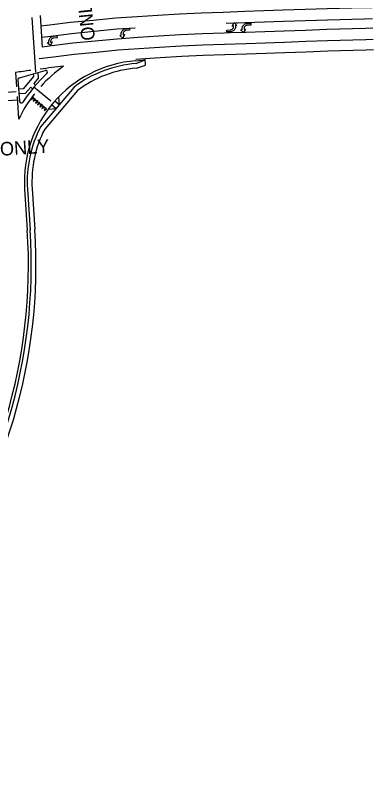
# Model space of a CAD drawing. Extents: x 979036 to 996074, y 1836928 to 1845163.
# Drawn here: x 982672 to 983052, y 1841869 to 1842691 of the extents above; entities that cross this region are included whole.
import ezdxf

# ---------------------------------------------------------------- set-up
doc = ezdxf.new("R2010")
doc.units = 0
for name, color, linetype in [('R_Proposed Road', 7, 'Continuous'), ('STRIPE_White Crosswalk', 7, 'Continuous'), ('STRIPE_White Stopbar', 7, 'Continuous'), ('STRIPE_White Turn Arrow', 7, 'Continuous'), ('STRIPE_WHITE_10_30 SKIP', 7, 'Continuous'), ('STRIPE_White_6in', 7, 'Continuous'), ('STRIPE_White_ONLY', 7, 'Continuous'), ('STRIPE_White_Yield Tri', 7, 'Continuous'), ('STRIPE_Yellow Dbl 6in', 7, 'Continuous'), ('STRIPE_Yellow_10_30 SKIP', 7, 'Continuous')]:
    doc.layers.add(name, color=color, linetype=linetype)

msp = doc.modelspace()

# ---------------------------------------------------------------- linework, layer by layer
at = {"layer": 'R_Proposed Road'}
for p, q in [((982799.93, 1842644.75), (982809.75, 1842645.53)), ((982800.05, 1842643.26), (982809.84, 1842644.23)), ((982800.28, 1842640.27), (982809.84, 1842644.23)), ((982810.26, 1842638.37), (982809.75, 1842645.53)), ((982676.32, 1842625.22), (982703.74, 1842632.98)), ((982800.68, 1842635.28), (982810.26, 1842638.37)), ((982691.2, 1842626.36), (982680.23, 1842613.3)), ((982691, 1842629.38), (982691.2, 1842626.36)), ((982696.32, 1842624.68), (982691.61, 1842619.08)), ((982695.92, 1842630.77), (982696.32, 1842624.68)), ((982674.87, 1842623.17), (982676.36, 1842600.28)), ((982688.39, 1842615.25), (982682.68, 1842608.45)), ((982690.41, 1842613.53), (982688.39, 1842615.25)), ((982693.65, 1842617.35), (982691.61, 1842619.08)), ((982734.54, 1842615.29), (982699.1, 1842573.54)), ((982680.23, 1842613.3), (982675.53, 1842613)), ((982682.68, 1842608.45), (982675.86, 1842608.01)), ((982738, 1842611.63), (982703.27, 1842570.73)), ((982718.44, 1842596.33), (982713.87, 1842600.21)), ((982717.78, 1842604.44), (982718.44, 1842596.33)), ((982707.09, 1842591.85), (982715.21, 1842592.51)), ((982715.21, 1842592.51), (982710.63, 1842596.39)), ((982681.97, 1842506.79), (982684.79, 1842463.51)), ((982684.96, 1842506.98), (982687.79, 1842463.71)), ((982689.95, 1842507.31), (982692.78, 1842464.03))]:
    msp.add_line(p, q, dxfattribs=at)
for centre, radius, start, end in [((982810.19, 1842515.16), 128.5, 94.53005, 183.73532), ((982810.19, 1842515.16), 125.5, 94.53005, 127.0701), ((982704.28, 1842631.05), 2, 312.42262, 105.79571), ((982810.19, 1842515.16), 120.5, 94.53005, 126.81019), ((982676.87, 1842623.3), 2, 105.79571, 183.73532), ((982810.19, 1842515.16), 155, 132.42262, 147.10941), ((982678.36, 1842600.42), 2, 183.73532, 327.10941), ((982810.19, 1842515.16), 125.5, 152.27794, 183.73532), ((982810.19, 1842515.16), 120.5, 152.53786, 183.73532), ((982120.82, 1842426.69), 565.17, 283.27832, 3.73532), ((982120.82, 1842426.69), 568.17, 283.27832, 3.73532), ((982120.82, 1842426.69), 573.17, 283.27832, 3.73532)]:
    msp.add_arc(centre, radius, start, end, dxfattribs=at)
at = {"layer": 'STRIPE_White Crosswalk'}
for p, q in [((982689.61, 1842689.06), (982693.4, 1842630.94)), ((982709.68, 1842600.21), (982691.87, 1842615.27)), ((982673.08, 1842610.34), (982627.82, 1842607.14))]:
    msp.add_line(p, q, dxfattribs=at)
at = {"layer": 'STRIPE_White Stopbar'}
for p, q in [((982698.49, 1842691.16), (982700.68, 1842657.65)), ((982674.29, 1842601.39), (982650.34, 1842599.83))]:
    msp.add_line(p, q, dxfattribs=at)
at = {"layer": 'STRIPE_White Turn Arrow'}
for points in [[(982902.15, 1842679.91), (982904.25, 1842683.73), (982907.41, 1842680.73), (982905.77, 1842680.47), (982905.81, 1842679.81), (982905.81, 1842679.23), (982905.69, 1842678.42), (982905.38, 1842677.46), (982905.01, 1842676.71), (982904.5, 1842676.08), (982903.91, 1842675.35), (982903.24, 1842674.92), (982902.53, 1842674.44), (982901.6, 1842674.12), (982900.63, 1842673.91), (982896.73, 1842673.74), (982896.64, 1842675.74), (982900.23, 1842675.93), (982900.92, 1842676.02), (982901.64, 1842676.28), (982902.39, 1842676.7), (982903, 1842677.31), (982903.2, 1842677.62), (982903.54, 1842678.26), (982903.74, 1842679.04), (982903.81, 1842679.78), (982903.79, 1842680.17)], [(982916.56, 1842676.88), (982914.44, 1842673.07), (982911.29, 1842676.09), (982912.94, 1842676.34), (982912.9, 1842677), (982912.91, 1842677.58), (982913.03, 1842678.39), (982913.34, 1842679.35), (982913.72, 1842680.1), (982914.23, 1842680.72), (982914.83, 1842681.45), (982915.49, 1842681.88), (982916.21, 1842682.35), (982917.14, 1842682.67), (982918.11, 1842682.88), (982922.01, 1842683.02), (982922.09, 1842681.02), (982918.5, 1842680.85), (982917.81, 1842680.77), (982917.09, 1842680.51), (982916.33, 1842680.09), (982915.72, 1842679.48), (982915.52, 1842679.17), (982915.18, 1842678.54), (982914.98, 1842677.76), (982914.9, 1842677.02), (982914.91, 1842676.63)], [(982788.13, 1842671.16), (982786.21, 1842667.24), (982782.91, 1842670.1), (982784.54, 1842670.43), (982784.47, 1842671.09), (982784.44, 1842671.67), (982784.53, 1842672.48), (982784.79, 1842673.46), (982785.13, 1842674.23), (982785.61, 1842674.88), (982786.16, 1842675.63), (982786.81, 1842676.1), (982787.5, 1842676.61), (982788.41, 1842676.97), (982789.37, 1842677.23), (982793.26, 1842677.57), (982793.44, 1842675.57), (982789.86, 1842675.22), (982789.18, 1842675.1), (982788.48, 1842674.81), (982787.74, 1842674.35), (982787.16, 1842673.72), (982786.97, 1842673.4), (982786.67, 1842672.74), (982786.5, 1842671.96), (982786.47, 1842671.22), (982786.5, 1842670.83)], [(982711.18, 1842663.18), (982709.26, 1842659.26), (982705.96, 1842662.12), (982707.59, 1842662.45), (982707.52, 1842663.11), (982707.49, 1842663.69), (982707.58, 1842664.5), (982707.84, 1842665.48), (982708.18, 1842666.25), (982708.66, 1842666.9), (982709.21, 1842667.65), (982709.86, 1842668.12), (982710.55, 1842668.62), (982711.46, 1842668.99), (982712.42, 1842669.24), (982716.31, 1842669.59), (982716.49, 1842667.59), (982712.91, 1842667.24), (982712.23, 1842667.12), (982711.53, 1842666.83), (982710.79, 1842666.37), (982710.21, 1842665.74), (982710.02, 1842665.41), (982709.72, 1842664.76), (982709.55, 1842663.98), (982709.52, 1842663.24), (982709.55, 1842662.85)]]:
    msp.add_lwpolyline(points, close=True, dxfattribs=at)
at = {"layer": 'STRIPE_WHITE_10_30 SKIP'}
for points in [[(982699.15, 1842680.13), (982708.42, 1842681.27), (982730.47, 1842683.98), (982754.66, 1842686.43), (982778.95, 1842688.89), (982801.31, 1842690.28), (982823.49, 1842691.67), (982846.45, 1842692.89), (982869.48, 1842694.11), (982892.65, 1842694.89), (982915.7, 1842695.67), (982936.09, 1842696.4), (982956.5, 1842697.12), (982979.85, 1842697.89), (983003.22, 1842698.65), (983016.23, 1842698.98), (983029.19, 1842699.31), (983042.16, 1842699.64), (983051, 1842699.86)], [(983052.02, 1842665.77), (983044.18, 1842665.52), (983030.57, 1842665.09), (983016.97, 1842664.66), (983003.37, 1842664.23), (982980.61, 1842663.48), (982957.87, 1842662.72), (982937.49, 1842662), (982917.1, 1842661.28), (982894.09, 1842660.49), (982871.18, 1842659.7), (982848.17, 1842658.57), (982825.2, 1842657.44), (982803.24, 1842655.86), (982781.29, 1842654.29), (982757.89, 1842652.04), (982734.51, 1842649.78), (982712.66, 1842647.05), (982697.41, 1842645.15)]]:
    msp.add_lwpolyline(points, dxfattribs=at)
at = {"layer": 'STRIPE_White_6in'}
for p, q in [((982672.37, 1842630.73), (982673.38, 1842615.36)), ((982674.03, 1842605.38), (982675.6, 1842581.36))]:
    msp.add_line(p, q, dxfattribs=at)
for points in [[(982900.32, 1842683.15), (982916.11, 1842683.68), (982936.51, 1842684.4), (982956.91, 1842685.13), (982980.24, 1842685.89), (983003.57, 1842686.66), (983016.53, 1842686.98), (983029.5, 1842687.31), (983042.46, 1842687.64), (983051.31, 1842687.87)], [(982699.99, 1842668.14), (982709.88, 1842669.36), (982731.81, 1842672.06), (982755.87, 1842674.49), (982779.93, 1842676.93), (982799.47, 1842678.15)], [(983051.64, 1842677.76), (983043.8, 1842677.51), (983030.19, 1842677.08), (983016.59, 1842676.65), (983002.98, 1842676.22), (982980.22, 1842675.47), (982957.45, 1842674.72), (982937.07, 1842674), (982916.68, 1842673.27), (982900.84, 1842672.73)], [(983052.36, 1842654.77), (983044.52, 1842654.52), (983030.92, 1842654.09), (983017.31, 1842653.66), (983003.72, 1842653.23), (982980.98, 1842652.48), (982958.24, 1842651.73), (982937.88, 1842651.01), (982917.48, 1842650.29), (982894.47, 1842649.5), (982871.64, 1842648.71), (982848.71, 1842647.58), (982825.87, 1842646.46), (982809.77, 1842645.3)]]:
    msp.add_lwpolyline(points, dxfattribs=at)
for centre, radius, start, end in [((982942.73, 1840768.39), 1881.86, 97.76526, 98.25994), ((982942.73, 1840768.39), 1881.86, 96.69647, 97.4619), ((982810.19, 1842515.16), 150, 125.40776, 137.83979), ((982810.19, 1842515.16), 150, 141.69874, 153.80888)]:
    msp.add_arc(centre, radius, start, end, dxfattribs=at)
at = {"layer": 'STRIPE_White_Yield Tri'}
for p, q in [((982690.08, 1842605), (982688.85, 1842602.11)), ((982688.85, 1842602.11), (982691.6, 1842603.71)), ((982691.6, 1842603.71), (982690.08, 1842605)), ((982692.37, 1842603.06), (982691.14, 1842600.17)), ((982691.14, 1842600.17), (982693.89, 1842601.77)), ((982693.89, 1842601.77), (982692.37, 1842603.06)), ((982694.66, 1842601.12), (982693.43, 1842598.23)), ((982693.43, 1842598.23), (982696.18, 1842599.83)), ((982696.18, 1842599.83), (982694.66, 1842601.12)), ((982696.95, 1842599.19), (982695.72, 1842596.29)), ((982698.47, 1842597.89), (982696.95, 1842599.19)), ((982695.72, 1842596.29), (982698.47, 1842597.89)), ((982699.24, 1842597.25), (982698.01, 1842594.36)), ((982698.01, 1842594.36), (982700.76, 1842595.96)), ((982700.76, 1842595.96), (982699.24, 1842597.25)), ((982701.53, 1842595.31), (982700.3, 1842592.42)), ((982700.3, 1842592.42), (982703.05, 1842594.02)), ((982703.05, 1842594.02), (982701.53, 1842595.31)), ((982703.82, 1842593.37), (982702.59, 1842590.48)), ((982702.59, 1842590.48), (982705.34, 1842592.08)), ((982705.34, 1842592.08), (982703.82, 1842593.37))]:
    msp.add_line(p, q, dxfattribs=at)
at = {"layer": 'STRIPE_Yellow Dbl 6in'}
msp.add_lwpolyline([(982899.68, 1842672.69), (982893.68, 1842672.48), (982870.67, 1842671.69), (982847.58, 1842670.55), (982824.48, 1842669.41), (982802.38, 1842667.83), (982780.29, 1842666.25), (982756.74, 1842663.98), (982733.19, 1842661.71), (982711.18, 1842658.96), (982700.68, 1842657.65)], dxfattribs=at)
at = {"layer": 'STRIPE_Yellow_10_30 SKIP'}
for points in [[(982895.87, 1842682.96), (982956.91, 1842685.13), (982980.24, 1842685.89), (983003.57, 1842686.66), (983016.53, 1842686.98), (983029.5, 1842687.31), (983042.46, 1842687.64), (983051.31, 1842687.87)], [(983051.64, 1842677.76), (983043.8, 1842677.51), (983030.19, 1842677.08), (983016.59, 1842676.65), (983002.98, 1842676.22), (982980.22, 1842675.47), (982957.45, 1842674.72), (982937.07, 1842674), (982916.68, 1842673.27), (982899.68, 1842672.69)]]:
    msp.add_lwpolyline(points, dxfattribs=at)

# ---------------------------------------------------------------- texts
at = {"layer": 'STRIPE_White_ONLY'}
for rotation, p in [(95.70664, (982756.73, 1842665.28)), (3.73532, (982656.22, 1842542.27))]:
    msp.add_text('ONLY', height=14.4, rotation=rotation, dxfattribs=at).set_placement(p)

doc.saveas('drawing.dxf')
